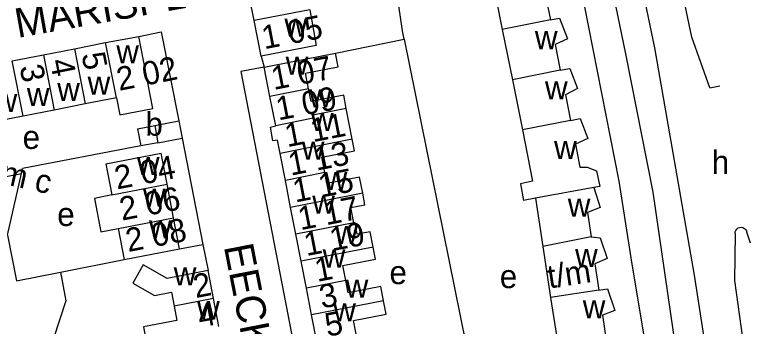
# Model space of a CAD drawing. Extents: x 161775 to 163181, y 382878 to 383925.
# Drawn here: x 163043.8 to 163171, y 383384.3 to 383437.4 of the extents above; entities that cross this region are included whole.
import ezdxf

# ---------------------------------------------------------------- set-up
doc = ezdxf.new("R2010")
doc.units = 0
for name, color, linetype in [('BLT_Basislijn', 7, 'Continuous'), ('BLT_Bebouwing', 7, 'Continuous'), ('BLT_Centroide', 7, 'Continuous'), ('BLT_Huisnummer', 7, 'Continuous'), ('BLT_Huisnummer_ tussenligend', 7, 'Continuous'), ('BLT_Huisnummer_reeks', 7, 'Continuous'), ('BLT_Onderverdeling_panden', 7, 'Continuous'), ('BLT_Straatnaam', 7, 'Continuous')]:
    doc.layers.add(name, color=color, linetype=linetype)

msp = doc.modelspace()

# ---------------------------------------------------------------- linework, layer by layer
at = {"layer": 'BLT_Basislijn'}
for p, q in [((163159.22, 383433.61), (163151.9, 383468.35)), ((163162.26, 383424.94), (163159.22, 383433.61)), ((163098.5, 383430.86), (163110.18, 383433.27)), ((163110.18, 383433.27), (163121.68, 383376.37)), ((163085.8, 383430.35), (163086.31, 383428.5)), ((163086.31, 383428.5), (163082.32, 383427.73)), ((163082.32, 383427.73), (163104.37, 383313.73)), ((163067.66, 383418.53), (163071.75, 383419.31)), ((163068.22, 383415.6), (163072.33, 383416.38)), ((163065.3, 383415.04), (163045.15, 383411.19)), ((163044.96, 383410.33), (163045.15, 383411.19)), ((163034.67, 383408.37), (163044.96, 383410.33)), ((163042.59, 383399.83), (163044.96, 383410.33)), ((163071.89, 383397.47), (163075.89, 383398.23)), ((163051.6, 383393.51), (163062.46, 383395.65)), ((163149, 383394.86), (163151.42, 383380.32))]:
    msp.add_line(p, q, dxfattribs=at)
for points in [[(163136.51, 383507.91), (163145.92, 383465.13), (163152.82, 383431.76)], [(163131.63, 383506.83), (163141.03, 383464.08), (163147.92, 383430.75)], [(163110.18, 383433.27), (163109.91, 383434.69), (163109.27, 383438.94), (163108.7, 383446.31), (163112.61, 383456.22), (163114.53, 383461.11), (163113.98, 383463.82)], [(163139.4, 383446.63), (163146.76, 383409.02), (163149, 383394.86)], [(163064.96, 383433.75), (163068.77, 383434.49), (163071.75, 383419.31)], [(163152.82, 383431.76), (163159.62, 383392.99), (163161.48, 383380.88)], [(163147.92, 383430.75), (163152.54, 383407.16), (163156.45, 383380.13)], [(163162.26, 383424.94), (163163.99, 383425.3)], [(163071.75, 383419.31), (163072.33, 383416.38)], [(163072.33, 383416.38), (163075.89, 383398.23)], [(163166.59, 383400.1), (163166.6, 383400.38), (163166.7, 383400.65), (163166.86, 383400.87), (163167.09, 383401.05), (163167.35, 383401.15), (163167.62, 383401.17), (163167.9, 383401.12), (163168.15, 383400.99), (163168.35, 383400.79), (163168.49, 383400.55), (163168.53, 383400.42)], [(163042.59, 383399.83), (163044.1, 383392.05), (163051.6, 383393.51)], [(163166.59, 383400.1), (163166.48, 383392.07), (163171, 383359.35)], [(163168.53, 383400.42), (163169.16, 383398.53)], [(163075.89, 383398.23), (163076.76, 383393.8)], [(163051.6, 383393.51), (163052.53, 383388.64), (163048.26, 383375.6), (163057.6, 383326.93)]]:
    msp.add_lwpolyline(points, dxfattribs=at)
at = {"layer": 'BLT_Bebouwing'}
for p, q in [((163125.19, 383443.48), (163126.9, 383434.93)), ((163084.61, 383436.43), (163083.47, 383442.3)), ((163094.11, 383438.27), (163095.19, 383432.16)), ((163085.8, 383430.35), (163084.61, 383436.43)), ((163126.9, 383434.93), (163128.61, 383426.33)), ((163059.3, 383432.67), (163064.96, 383433.75)), ((163054, 383431.64), (163059.3, 383432.67)), ((163048.7, 383430.61), (163054, 383431.64)), ((163095.19, 383432.16), (163085.8, 383430.35)), ((163043.4, 383429.58), (163048.7, 383430.61)), ((163087.29, 383423.49), (163086.31, 383428.5)), ((163128.61, 383426.33), (163130.32, 383417.77)), ((163088.28, 383418.49), (163087.29, 383423.49)), ((163055.83, 383422.21), (163050.52, 383421.18)), ((163061.13, 383423.23), (163055.83, 383422.21)), ((163050.52, 383421.18), (163045.22, 383420.15)), ((163101.33, 383416.18), (163100.32, 383421.43)), ((163045.22, 383420.15), (163039.92, 383419.12)), ((163064.75, 383417.98), (163067.66, 383418.53)), ((163067.66, 383418.53), (163068.22, 383415.6)), ((163064.75, 383417.98), (163065.3, 383415.04)), ((163130.32, 383417.77), (163132.07, 383409.02)), ((163068.22, 383415.6), (163065.3, 383415.04)), ((163059.33, 383411.97), (163068.74, 383413.8)), ((163069.77, 383408.5), (163068.74, 383413.8)), ((163089.94, 383409.17), (163089.05, 383413.77)), ((163059.33, 383411.97), (163060.35, 383406.68)), ((163070.87, 383402.77), (163069.77, 383408.5)), ((163090.8, 383404.57), (163089.94, 383409.17)), ((163132.07, 383409.02), (163129.99, 383408.6)), ((163129.99, 383408.6), (163130.49, 383405.75)), ((163143.54, 383408.15), (163142.48, 383407.96)), ((163132.54, 383406.16), (163130.49, 383405.75)), ((163132.54, 383406.16), (163133.81, 383397.87)), ((163091.71, 383399.98), (163090.8, 383404.57)), ((163071.89, 383397.47), (163070.87, 383402.77)), ((163061.45, 383400.96), (163062.46, 383395.65)), ((163092.61, 383395.39), (163091.71, 383399.98)), ((163062.46, 383395.65), (163071.89, 383397.47)), ((163133.81, 383397.87), (163135.14, 383389.21)), ((163093.51, 383390.8), (163092.61, 383395.39)), ((163094.41, 383386.21), (163093.51, 383390.8)), ((163135.14, 383389.21), (163136.45, 383380.64)), ((163078.59, 383384.23), (163077.68, 383389.01)), ((163095.32, 383381.62), (163094.41, 383386.21))]:
    msp.add_line(p, q, dxfattribs=at)
for points in [[(163133.37, 383445.11), (163134.83, 383445.4), (163136.2, 383441.89), (163134.22, 383440.96), (163135.09, 383436.57)], [(163135.09, 383436.57), (163136.62, 383436.87), (163138, 383433.35), (163135.91, 383432.35), (163136.78, 383427.96)], [(163061.13, 383423.23), (163061.71, 383420.35), (163067.34, 383421.44), (163064.96, 383433.75)], [(163086.31, 383428.5), (163091.22, 383429.46), (163098.5, 383430.86)], [(163093.88, 383424.79), (163093.37, 383427.48), (163098.94, 383428.55), (163098.5, 383430.86)], [(163136.78, 383427.96), (163138.39, 383428.28), (163139.73, 383424.84), (163137.67, 383423.75), (163138.54, 383419.41)], [(163100.32, 383421.43), (163099.88, 383423.71), (163094.3, 383422.63), (163093.88, 383424.79)], [(163138.54, 383419.41), (163140.15, 383419.73), (163141.46, 383416.33), (163139.37, 383415.33), (163140.14, 383411.44), (163141.37, 383411.44), (163142.98, 383410.82), (163143.54, 383408.15)], [(163089.05, 383413.77), (163088.61, 383416.05), (163087.82, 383415.91), (163087.41, 383418.27), (163088.28, 383418.49)], [(163096.65, 383410.49), (163096.14, 383413.11), (163101.71, 383414.2), (163101.33, 383416.18)], [(163103.11, 383406.99), (163102.58, 383409.72), (163097.01, 383408.64), (163096.65, 383410.49)], [(163101.6, 383401.93), (163101.08, 383404.56), (163103.49, 383405.03), (163103.11, 383406.99)], [(163142.48, 383407.96), (163143.59, 383404.52), (163141.42, 383403.72), (163142.06, 383399.52)], [(163060.35, 383406.68), (163057.41, 383406.1), (163058.51, 383400.39), (163061.45, 383400.96)], [(163104.89, 383397.8), (163104.38, 383400.4), (163102.19, 383399.97), (163101.8, 383401.97), (163101.6, 383401.93)], [(163142.06, 383399.52), (163143.57, 383399.35), (163144.78, 383395.84), (163142.67, 383394.93), (163143.35, 383390.46)], [(163100.21, 383392.11), (163099.72, 383394.64), (163105.29, 383395.72), (163104.89, 383397.8)], [(163065.71, 383394.75), (163063.94, 383391.61), (163067.62, 383389.52), (163070.53, 383390.08), (163070.97, 383387.73)], [(163076.76, 383393.8), (163069.76, 383392.46), (163065.71, 383394.75)], [(163077.68, 383389.01), (163076.76, 383393.8)], [(163106.66, 383388.61), (163106.19, 383391.06), (163100.62, 383389.97), (163100.21, 383392.11)], [(163143.35, 383390.46), (163144.82, 383390.69), (163146.1, 383386.97), (163143.97, 383386.16), (163144.62, 383381.89)], [(163101.98, 383382.93), (163101.53, 383385.28), (163107.1, 383386.36), (163106.66, 383388.61)], [(163070.97, 383387.73), (163071.45, 383385.26), (163065.76, 383384.17), (163066.18, 383381.98)]]:
    msp.add_lwpolyline(points, dxfattribs=at)
at = {"layer": 'BLT_Onderverdeling_panden'}
for p, q in [((163094.11, 383438.27), (163084.61, 383436.43)), ((163135.09, 383436.57), (163126.9, 383434.93)), ((163061.13, 383423.23), (163059.3, 383432.67)), ((163054, 383431.64), (163055.83, 383422.21)), ((163048.7, 383430.61), (163050.52, 383421.18)), ((163045.22, 383420.15), (163043.4, 383429.58)), ((163136.78, 383427.96), (163128.61, 383426.33)), ((163093.88, 383424.79), (163087.29, 383423.49)), ((163138.54, 383419.41), (163130.32, 383417.77)), ((163101.33, 383416.18), (163089.05, 383413.77)), ((163096.65, 383410.49), (163089.94, 383409.17)), ((163103.11, 383406.99), (163090.8, 383404.57)), ((163142.48, 383407.96), (163132.54, 383406.16)), ((163101.6, 383401.93), (163091.71, 383399.98)), ((163142.06, 383399.52), (163133.81, 383397.87)), ((163104.89, 383397.8), (163092.61, 383395.39)), ((163143.35, 383390.46), (163135.14, 383389.21)), ((163077.68, 383389.01), (163070.97, 383387.73))]:
    msp.add_line(p, q, dxfattribs=at)
for points in [[(163100.32, 383421.43), (163094.59, 383420.3), (163094.69, 383419.78), (163088.28, 383418.49)], [(163060.35, 383406.68), (163069.77, 383408.5)], [(163061.45, 383400.96), (163070.87, 383402.77)], [(163100.21, 383392.11), (163093.51, 383390.8)], [(163106.66, 383388.61), (163094.41, 383386.21)]]:
    msp.add_lwpolyline(points, dxfattribs=at)

# ---------------------------------------------------------------- texts
at = {"layer": 'BLT_Centroide'}
for s, p in [('w', (163089.78, 383433.68)), ('w', (163132.45, 383431.56)), ('w', (163061.12, 383429.17)), ('w', (163089.99, 383427.19)), ('w', (163056.23, 383423.78)), ('w', (163134.17, 383422.98)), ('w', (163045.88, 383421.85)), ('w', (163051.05, 383422.74)), ('w', (163093.97, 383421.62)), ('w', (163040.38, 383420.85)), ('b', (163066.08, 383416.79)), ('w', (163094.3, 383417.59)), ('e', (163045.15, 383414.54)), ('w', (163135.72, 383412.81)), ('w', (163092.74, 383412.69)), ('h', (163162.59, 383410.28)), ('w', (163064.63, 383410.09)), ('w', (163096.62, 383407.53)), ('w', (163065.66, 383404.69)), ('w', (163094.51, 383403.5)), ('w', (163138.06, 383402.98)), ('e', (163051.05, 383401.39)), ('w', (163066.69, 383399.31)), ('w', (163098.41, 383398.34)), ('w', (163096.3, 383394.31)), ('w', (163139.3, 383394.41)), ('w', (163070.91, 383391.25)), ('e', (163107.67, 383391.47)), ('e', (163126.47, 383390.79)), ('w', (163100.2, 383389.16)), ('w', (163074.88, 383385.5)), ('w', (163098.09, 383385.12)), ('w', (163140.61, 383385.66))]:
    msp.add_text(s, height=4, dxfattribs=at).set_placement(p)
at = {"layer": 'BLT_Huisnummer'}
for s, rotation, p in [('1 05', 10.9549, (163086.32, 383431.53)), ('5', 281.369, (163055.18, 383430.67)), ('2 02', 11.369, (163061.6, 383424.43)), ('1 07', 10.9549, (163087.94, 383424.59)), ('3', 281.369, (163044.61, 383428.56)), ('1 11', 10.9549, (163090.24, 383414.83)), ('2 04', 10.9549, (163061.23, 383407.61)), ('1 15', 10.9549, (163091.6, 383405.38)), ('2 08', 10.9549, (163063.13, 383396.93)), ('1 19', 10.9549, (163093.52, 383396.25)), ('1', 11.0211, (163095.35, 383391.84)), ('2', 10.8142, (163074.65, 383389.08)), ('5', 11.0211, (163097.08, 383382.48))]:
    msp.add_text(s, height=4, rotation=rotation, dxfattribs=at).set_placement(p)
at = {"layer": 'BLT_Huisnummer_ tussenligend'}
for s, rotation, p in [('4', 281.369, (163049.78, 383429.57)), ('1 09', 10.955, (163088.74, 383419.39)), ('1 13', 10.955, (163090.83, 383409.97)), ('2 06', 10.955, (163062.07, 383402.29)), ('1 17', 10.955, (163092.5, 383400.66)), ('3', 11.0211, (163096.15, 383387.29)), ('4', 10.8142, (163075.38, 383384.05))]:
    msp.add_text(s, height=4, rotation=rotation, dxfattribs=at).set_placement(p)
at = {"layer": 'BLT_Huisnummer_reeks'}
for s, rotation, p in [('26-a t/m c', 347.2509, (163026.4, 383412.06)), ('t/m', 8.7006, (163134.9, 383390.72))]:
    msp.add_text(s, height=4, rotation=rotation, dxfattribs=at).set_placement(p)
at = {"layer": 'BLT_Straatnaam'}
for s, height, rotation, p in [('JACOB MARISPLEIN', 4.9999, 10.1366, (163020.54, 383429.22)), ('EECKHOUTSTRAAT', 5, 281.0751, (163079.43, 383397.91))]:
    msp.add_text(s, height=height, rotation=rotation, dxfattribs=at).set_placement(p)

doc.saveas('drawing.dxf')
